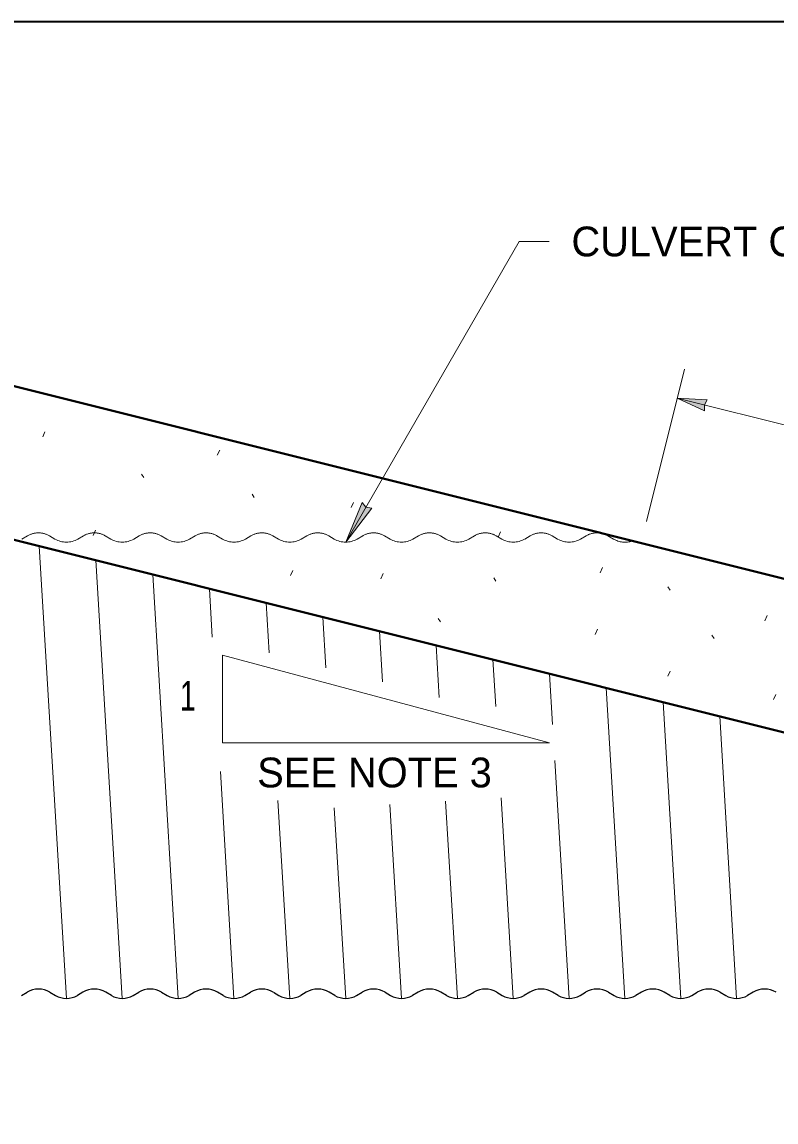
# Model space of a CAD drawing. Extents: x 99860 to 103153, y 99998 to 102077.
# Drawn here: x 100937 to 101342, y 101485 to 102076 of the extents above; entities that cross this region are included whole.
import ezdxf
from ezdxf.enums import TextEntityAlignment as Align

# ---------------------------------------------------------------- set-up
doc = ezdxf.new("R2010")
doc.units = 0
doc.header["$LTSCALE"] = 6.4
doc.linetypes.add('MEDIUM_DASHED', pattern=[4.5, 3, -1.5])
for name, color, linetype, lineweight in [('1', 7, 'Continuous', 13), ('13', 7, 'Continuous', 40), ('15', 7, 'Continuous', 13), ('17', 7, 'Continuous', 13), ('20', 7, 'Continuous', 13)]:
    doc.layers.add(name, color=color, linetype=linetype, lineweight=lineweight)

msp = doc.modelspace()

# ---------------------------------------------------------------- hatches: boundary and pattern name
at = {"layer": '15'}
for points in [[(101289.259, 101873.466), (101303.767, 101866.66), (101303.808, 101869.829), (101305.263, 101872.644)], [(101111.12, 101796.125), (101125.119, 101814.403), (101122.005, 101814.979), (101119.949, 101817.388)]]:
    msp.add_hatch(color=256, dxfattribs=at).paths.add_polyline_path(points)

# ---------------------------------------------------------------- linework, layer by layer
at = {"layer": '1', "linetype": 'MEDIUM_DASHED'}
for p, q in [((100940.246, 101799.589), (100937.259, 101797.811)), ((100938.07, 101796.125), (101898.063, 101556.125)), ((100954.982, 101797.811), (100951.995, 101799.589)), ((100970.246, 101799.589), (100967.259, 101797.811)), ((100984.982, 101797.811), (100981.995, 101799.589)), ((100984.982, 101797.811), (100981.995, 101799.589)), ((101000.246, 101799.589), (100997.259, 101797.811)), ((101000.246, 101799.589), (100997.259, 101797.811)), ((101014.982, 101797.811), (101011.995, 101799.589)), ((101030.246, 101799.589), (101027.259, 101797.811)), ((101044.982, 101797.811), (101041.995, 101799.589)), ((101060.246, 101799.589), (101057.259, 101797.811)), ((101074.982, 101797.811), (101071.995, 101799.589)), ((101090.246, 101799.589), (101087.259, 101797.811)), ((101104.982, 101797.811), (101101.995, 101799.589)), ((101120.246, 101799.589), (101117.259, 101797.811)), ((101134.982, 101797.811), (101131.995, 101799.589)), ((101150.246, 101799.589), (101147.259, 101797.811)), ((101164.982, 101797.811), (101161.995, 101799.589)), ((101180.246, 101799.589), (101177.259, 101797.811)), ((101194.982, 101797.811), (101191.995, 101799.589)), ((101210.246, 101799.589), (101207.259, 101797.811)), ((101224.982, 101797.811), (101221.995, 101799.589)), ((101240.246, 101799.589), (101237.259, 101797.811)), ((101254.982, 101797.811), (101251.995, 101799.589)), ((101267.498, 101796.125), (101472.62, 101744.771)), ((101267.916, 101796.125), (101472.662, 101744.938))]:
    msp.add_line(p, q, dxfattribs=at)
at = {"layer": '1'}
for p, q in [((100961.12, 101551.125), (100946.548, 101794.006)), ((100991.12, 101551.125), (100977.005, 101786.391)), ((101021.12, 101551.125), (101007.461, 101778.777)), ((101039.483, 101745.09), (101037.918, 101771.163)), ((101069.99, 101736.627), (101068.375, 101763.549)), ((101100.468, 101728.659), (101098.832, 101755.934)), ((101130.915, 101721.216), (101129.289, 101748.32)), ((101161.421, 101712.783), (101159.746, 101740.706)), ((101044.932, 101688.439), (101044.932, 101735.452)), ((101220.611, 101688.439), (101044.932, 101735.452)), ((101191.714, 101707.904), (101190.202, 101733.091)), ((101222.29, 101698.302), (101220.659, 101725.477)), ((101261.12, 101551.125), (101251.116, 101717.863)), ((101291.12, 101551.125), (101281.573, 101710.249)), ((101321.12, 101551.125), (101312.03, 101702.634)), ((101044.932, 101688.439), (101220.611, 101688.439)), ((101231.12, 101551.125), (101223.452, 101678.938)), ((101051.12, 101551.125), (101043.814, 101672.899)), ((101081.12, 101551.125), (101074.748, 101657.337)), ((101111.12, 101551.125), (101104.976, 101653.53)), ((101141.12, 101551.125), (101134.869, 101655.323)), ((101171.12, 101551.125), (101164.761, 101657.117)), ((101201.12, 101551.125), (101194.653, 101658.91))]:
    msp.add_line(p, q, dxfattribs=at)
at = {"layer": '1', "lineweight": 25}
for p, q in [((100936.995, 101552.662), (100939.982, 101554.439)), ((100952.259, 101554.439), (100955.246, 101552.662)), ((100969.982, 101554.439), (100966.995, 101552.662)), ((100985.246, 101552.662), (100982.259, 101554.439)), ((100996.995, 101552.662), (100999.982, 101554.439)), ((101012.259, 101554.439), (101015.246, 101552.662)), ((101029.982, 101554.439), (101026.995, 101552.662)), ((101045.246, 101552.662), (101042.259, 101554.439)), ((101056.995, 101552.662), (101059.982, 101554.439)), ((101072.259, 101554.439), (101075.246, 101552.662)), ((101089.982, 101554.439), (101086.995, 101552.662)), ((101105.246, 101552.662), (101102.259, 101554.439)), ((101116.995, 101552.662), (101119.982, 101554.439)), ((101132.259, 101554.439), (101135.246, 101552.662)), ((101149.982, 101554.439), (101146.995, 101552.662)), ((101165.246, 101552.662), (101162.259, 101554.439)), ((101176.995, 101552.662), (101179.982, 101554.439)), ((101192.259, 101554.439), (101195.246, 101552.662)), ((101209.982, 101554.439), (101206.995, 101552.662)), ((101225.246, 101552.662), (101222.259, 101554.439)), ((101236.995, 101552.662), (101239.982, 101554.439)), ((101252.259, 101554.439), (101255.246, 101552.662)), ((101269.982, 101554.439), (101266.995, 101552.662)), ((101285.246, 101552.662), (101282.259, 101554.439)), ((101296.995, 101552.662), (101299.982, 101554.439)), ((101312.259, 101554.439), (101315.246, 101552.662)), ((101329.982, 101554.439), (101326.995, 101552.662))]:
    msp.add_line(p, q, dxfattribs=at)
at = {"layer": '1', "lineweight": 35}
msp.add_lwpolyline([(99862, 99999.5), (103151, 99999.5), (103151, 102075.5), (99862, 102075.5)], close=True, dxfattribs=at)
at = {"layer": '1', "linetype": 'MEDIUM_DASHED'}
msp.add_lwpolyline([(100940.246, 101799.589), (100937.259, 101797.811), (100937.258, 101797.813)], dxfattribs=at)
for centre, start, end in [((100946.12, 101789.125), 90, 119.31291), ((100946.12, 101789.125), 90, 119.31291), ((100946.12, 101789.125), 60.68709, 90), ((100976.12, 101789.125), 90, 119.31291), ((100976.12, 101789.125), 60.68709, 90), ((100976.12, 101789.125), 60.68709, 90), ((101006.12, 101789.125), 90, 119.31291), ((101006.12, 101789.125), 90, 119.31291), ((101006.12, 101789.125), 60.68709, 90), ((101036.12, 101789.125), 90, 119.31291), ((101036.12, 101789.125), 60.68709, 90), ((101066.12, 101789.125), 90, 119.31291), ((101066.12, 101789.125), 60.68709, 90), ((101096.12, 101789.125), 90, 119.31291), ((101096.12, 101789.125), 60.68709, 90), ((101126.12, 101789.125), 90, 119.31291), ((101126.12, 101789.125), 60.68709, 90), ((101156.12, 101789.125), 90, 119.31291), ((101156.12, 101789.125), 60.68709, 90), ((101186.12, 101789.125), 90, 119.31291), ((101186.12, 101789.125), 60.68709, 90), ((101216.12, 101789.125), 90, 119.31291), ((101216.12, 101789.125), 60.68709, 90), ((101246.12, 101789.125), 90, 119.31291), ((101246.12, 101789.125), 60.68709, 90), ((100961.12, 101808.125), 239.24007, 300.75993), ((100991.12, 101808.125), 239.24007, 300.75993), ((100991.12, 101808.125), 239.24007, 300.75993), ((101021.12, 101808.125), 239.24007, 300.75993), ((101051.12, 101808.125), 239.24007, 300.75993), ((101081.12, 101808.125), 239.24007, 300.75993), ((101111.12, 101808.125), 239.24007, 300.75993), ((101141.12, 101808.125), 239.24007, 300.75993), ((101171.12, 101808.125), 239.24007, 300.75993), ((101201.12, 101808.125), 239.24007, 300.75993), ((101231.12, 101808.125), 239.24007, 300.75993), ((101261.12, 101808.125), 239.24007, 288.68429)]:
    msp.add_arc(centre, 12, start, end, dxfattribs=at)
at = {"layer": '1', "lineweight": 25}
for centre, start, end in [((100946.12, 101544.125), 59.24007, 120.75992), ((100961.12, 101563.125), 240.68709, 270), ((100961.12, 101563.125), 270, 299.31291), ((100976.12, 101544.125), 59.24007, 120.75993), ((100991.12, 101563.125), 240.68709, 270), ((100991.12, 101563.125), 270, 299.31291), ((101006.12, 101544.125), 59.24007, 120.75992), ((101021.12, 101563.125), 240.68709, 270), ((101021.12, 101563.125), 270, 299.31291), ((101036.12, 101544.125), 59.24007, 120.75993), ((101051.12, 101563.125), 240.68709, 270), ((101051.12, 101563.125), 270, 299.31291), ((101066.12, 101544.125), 59.24007, 120.75992), ((101081.12, 101563.125), 240.68709, 270), ((101081.12, 101563.125), 270, 299.31291), ((101096.12, 101544.125), 59.24007, 120.75993), ((101111.12, 101563.125), 240.68709, 270), ((101111.12, 101563.125), 270, 299.31291), ((101126.12, 101544.125), 59.24007, 120.75992), ((101141.12, 101563.125), 240.68709, 270), ((101141.12, 101563.125), 270, 299.31291), ((101156.12, 101544.125), 59.24007, 120.75993), ((101171.12, 101563.125), 240.68709, 270), ((101171.12, 101563.125), 270, 299.31291), ((101186.12, 101544.125), 59.24007, 120.75992), ((101201.12, 101563.125), 240.68709, 270), ((101201.12, 101563.125), 270, 299.31291), ((101216.12, 101544.125), 59.24007, 120.75993), ((101231.12, 101563.125), 240.68709, 270), ((101231.12, 101563.125), 270, 299.31291), ((101246.12, 101544.125), 59.24007, 120.75992), ((101261.12, 101563.125), 240.68709, 270), ((101261.12, 101563.125), 270, 299.31291), ((101276.12, 101544.125), 59.24007, 120.75993), ((101291.12, 101563.125), 240.68709, 270), ((101291.12, 101563.125), 270, 299.31291), ((101306.12, 101544.125), 59.24007, 120.75992), ((101321.12, 101563.125), 240.68709, 270), ((101321.12, 101563.125), 270, 299.31291), ((101336.12, 101544.125), 59.24007, 120.75993)]:
    msp.add_arc(centre, 12, start, end, dxfattribs=at)
at = {"layer": '13'}
for p, q in [((100899.264, 101888.289), (102226.12, 101556.572)), ((102146.12, 101494.11), (100879.861, 101810.677))]:
    msp.add_line(p, q, dxfattribs=at)
at = {"layer": '15'}
for p, q in [((101111.12, 101796.125), (101204.366, 101957.631)), ((101204.367, 101957.631), (101220.367, 101957.631)), ((101293.14, 101888.988), (101272.716, 101807.294)), ((101470.703, 101828.105), (101289.259, 101873.466))]:
    msp.add_line(p, q, dxfattribs=at)
for points in [[(101289.259, 101873.466), (101303.767, 101866.66), (101303.808, 101869.829), (101305.263, 101872.644)], [(101111.12, 101796.125), (101125.119, 101814.403), (101122.005, 101814.979), (101119.949, 101817.388)]]:
    msp.add_lwpolyline(points, close=True, dxfattribs=at)
at = {"layer": '17'}
for p, q in [((100948.368, 101852.679), (100949.608, 101855.449)), ((101042.143, 101842.834), (101043.453, 101845.594)), ((101001.431, 101832.714), (101002.611, 101830.914)), ((101060.868, 101821.964), (101062.048, 101820.094)), ((101114.001, 101814.731), (101115.241, 101817.501)), ((100975.495, 101799.74), (100976.745, 101802.51)), ((101192.988, 101798.895), (101194.298, 101801.655)), ((101081.507, 101778.161), (101082.757, 101780.921)), ((101130.059, 101776.499), (101131.309, 101779.269)), ((101247.807, 101779.757), (101249.047, 101782.527)), ((101190.613, 101777.05), (101191.793, 101775.18)), ((101284.195, 101772.199), (101285.375, 101770.399)), ((101160.806, 101755.122), (101161.986, 101753.322)), ((101336.2, 101753.929), (101337.51, 101756.689)), ((101245.19, 101746.587), (101246.44, 101749.347)), ((101307.855, 101746.249), (101309.035, 101744.379)), ((101284.158, 101724.093), (101285.408, 101726.863)), ((101340.829, 101711.591), (101342.079, 101714.351))]:
    msp.add_line(p, q, dxfattribs=at)

# ---------------------------------------------------------------- texts
at = {"layer": '20'}
msp.add_text('CULVERT CROWN', height=16, dxfattribs=at).set_placement((101232.367, 101949.631))
at = {"layer": '20', "width": 0.7}
msp.add_text('1', height=16, dxfattribs=at).set_placement((101022.146, 101705.624))
at = {"layer": '20'}
msp.add_text('SEE NOTE 3', height=16, dxfattribs=at).set_placement((101126.604, 101664.439), align=Align.CENTER)

doc.saveas('drawing.dxf')
